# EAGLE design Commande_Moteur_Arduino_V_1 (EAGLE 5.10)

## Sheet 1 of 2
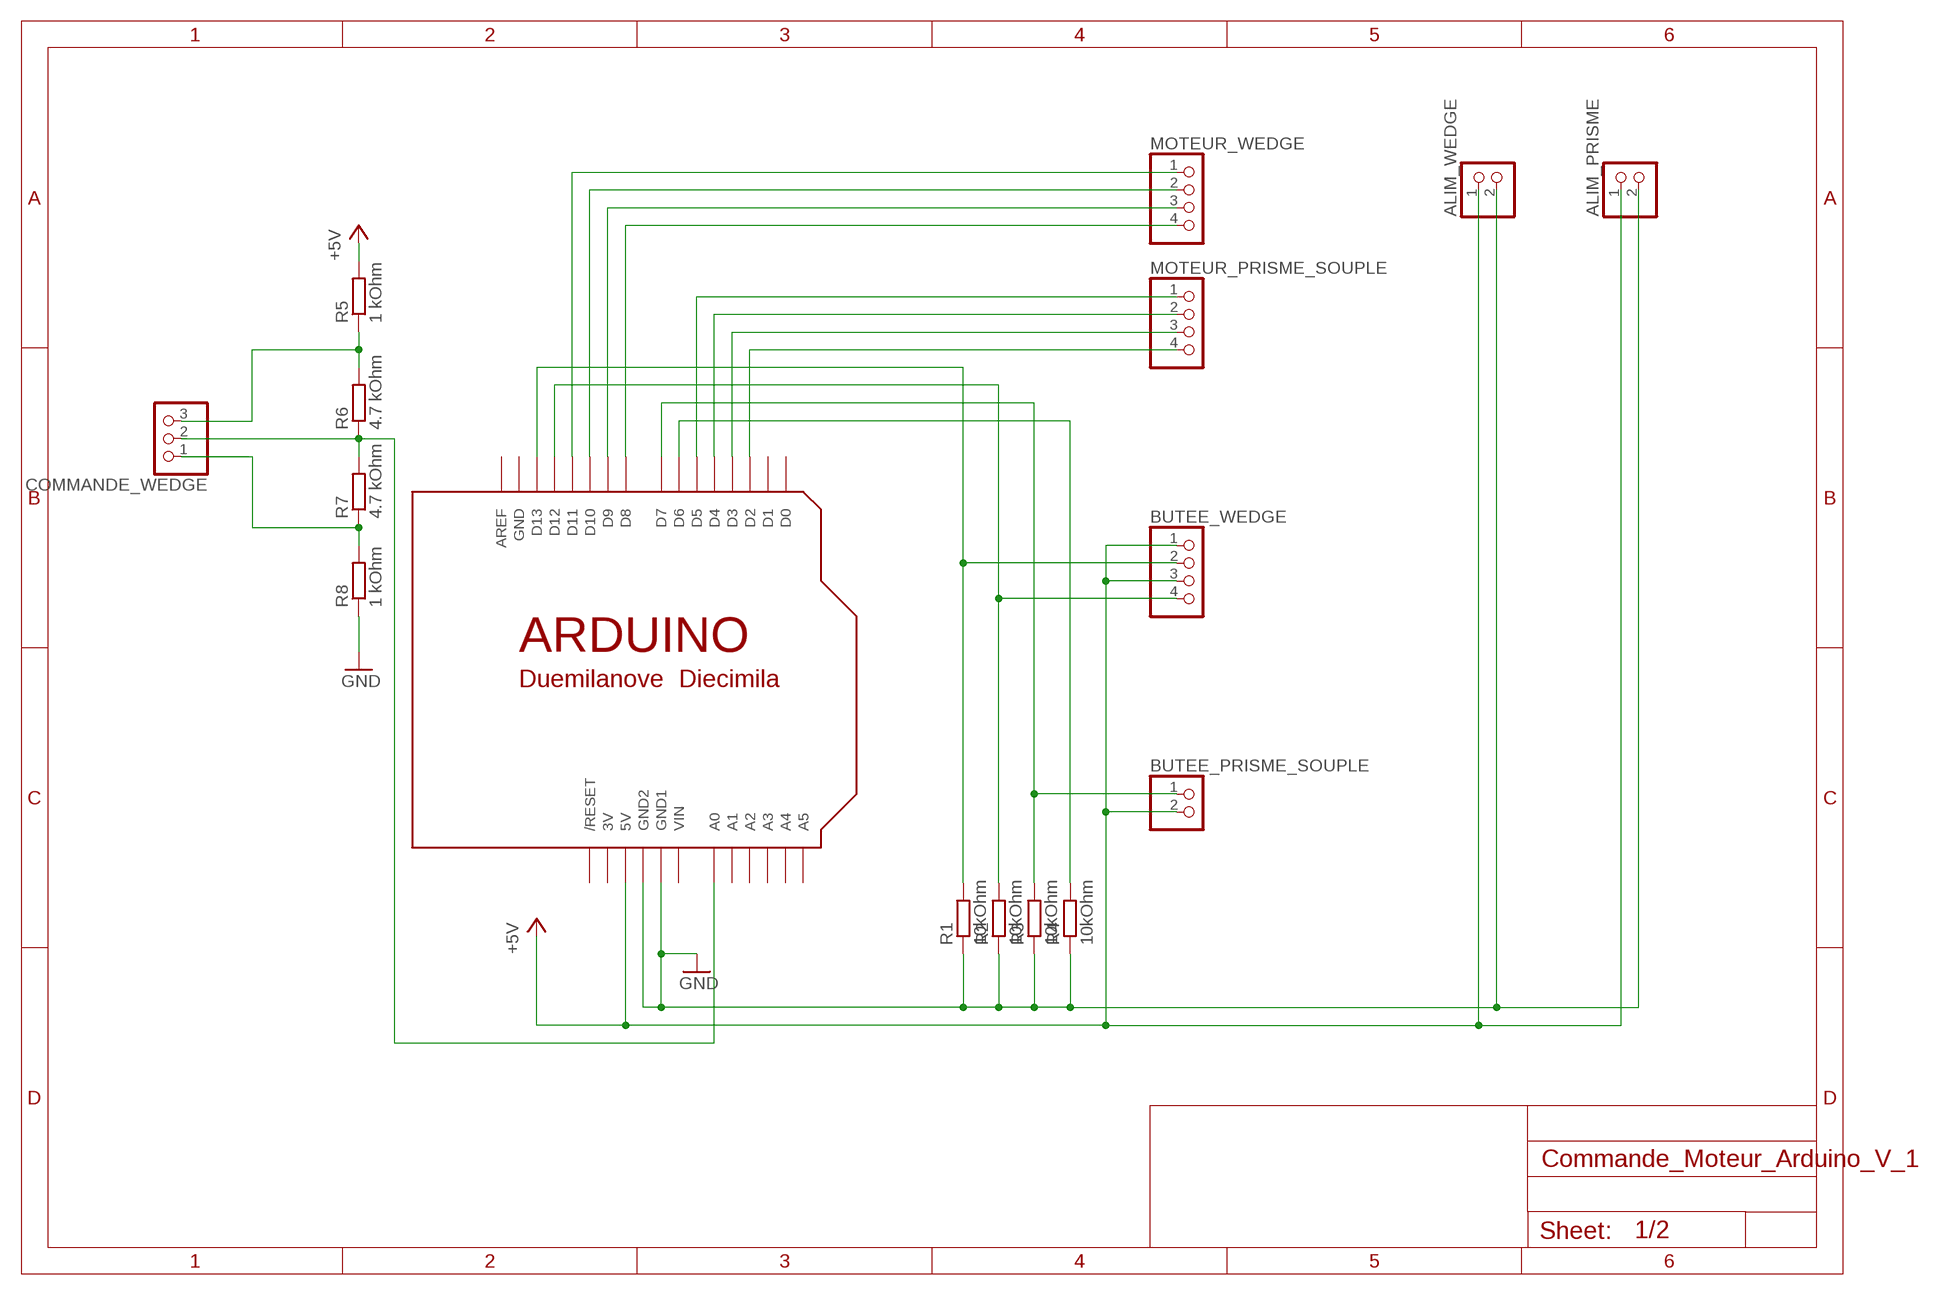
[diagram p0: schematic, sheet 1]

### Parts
ALIM_PRISME  PINHD-1X2  [1X02]
ALIM_WEDGE  PINHD-1X2  [1X02]
BUTEE_PRISME_SOUPLE  PINHD-1X2  [1X02]
BUTEE_WEDGE  PINHD-1X4  [1X04]
COMMANDE_WEDGE  PINHD-1X3  [1X03]
MOTEUR_PRISME_SOUPLE  PINHD-1X4  [1X04]
MOTEUR_WEDGE  PINHD-1X4  [1X04]
R1  10kOhm  R-EU_0204/7  [0204/7]
R2  10kOhm  R-EU_0204/7  [0204/7]
R3  10kOhm  R-EU_0204/7  [0204/7]
R4  10kOhm  R-EU_0204/7  [0204/7]
R5  1 kOhm  R-EU_0204/7  [0204/7]
R6  4.7 kOhm  R-EU_0204/7  [0204/7]
R7  4.7 kOhm  R-EU_0204/7  [0204/7]
R8  1 kOhm  R-EU_0204/7  [0204/7]
U$1  ARDUINOUNO  [ARDUINO]

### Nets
+5V: ALIM_PRISME.1 ALIM_WEDGE.1 BUTEE_PRISME_SOUPLE.2 BUTEE_WEDGE.1 BUTEE_WEDGE.3 R5.2 U$1.5V
GND: ALIM_PRISME.2 ALIM_WEDGE.2 R1.1 R2.1 R3.1 R4.1 R8.1 U$1.GND1 U$1.GND2
N$1: MOTEUR_WEDGE.4 U$1.D8
N$2: MOTEUR_WEDGE.3 U$1.D9
N$3: MOTEUR_WEDGE.2 U$1.D10
N$4: MOTEUR_WEDGE.1 U$1.D11
N$5: MOTEUR_PRISME_SOUPLE.4 U$1.D2
N$6: MOTEUR_PRISME_SOUPLE.3 U$1.D3
N$7: MOTEUR_PRISME_SOUPLE.2 U$1.D4
N$8: MOTEUR_PRISME_SOUPLE.1 U$1.D5
N$9: COMMANDE_WEDGE.3 R5.1 R6.2
N$10: BUTEE_WEDGE.2 R1.2 U$1.D13
N$11: BUTEE_WEDGE.4 R2.2 U$1.D12
N$12: BUTEE_PRISME_SOUPLE.1 R3.2 U$1.D7
N$13: R4.2 U$1.D6
N$14: COMMANDE_WEDGE.2 R6.1 R7.2 U$1.A0
N$15: COMMANDE_WEDGE.1 R7.1 R8.2
Unconnected: U$1.A1 U$1.A2 U$1.A3 U$1.A4 U$1.A5 U$1.AREF U$1.D0 U$1.D1 U$1.RESET(/RESET)

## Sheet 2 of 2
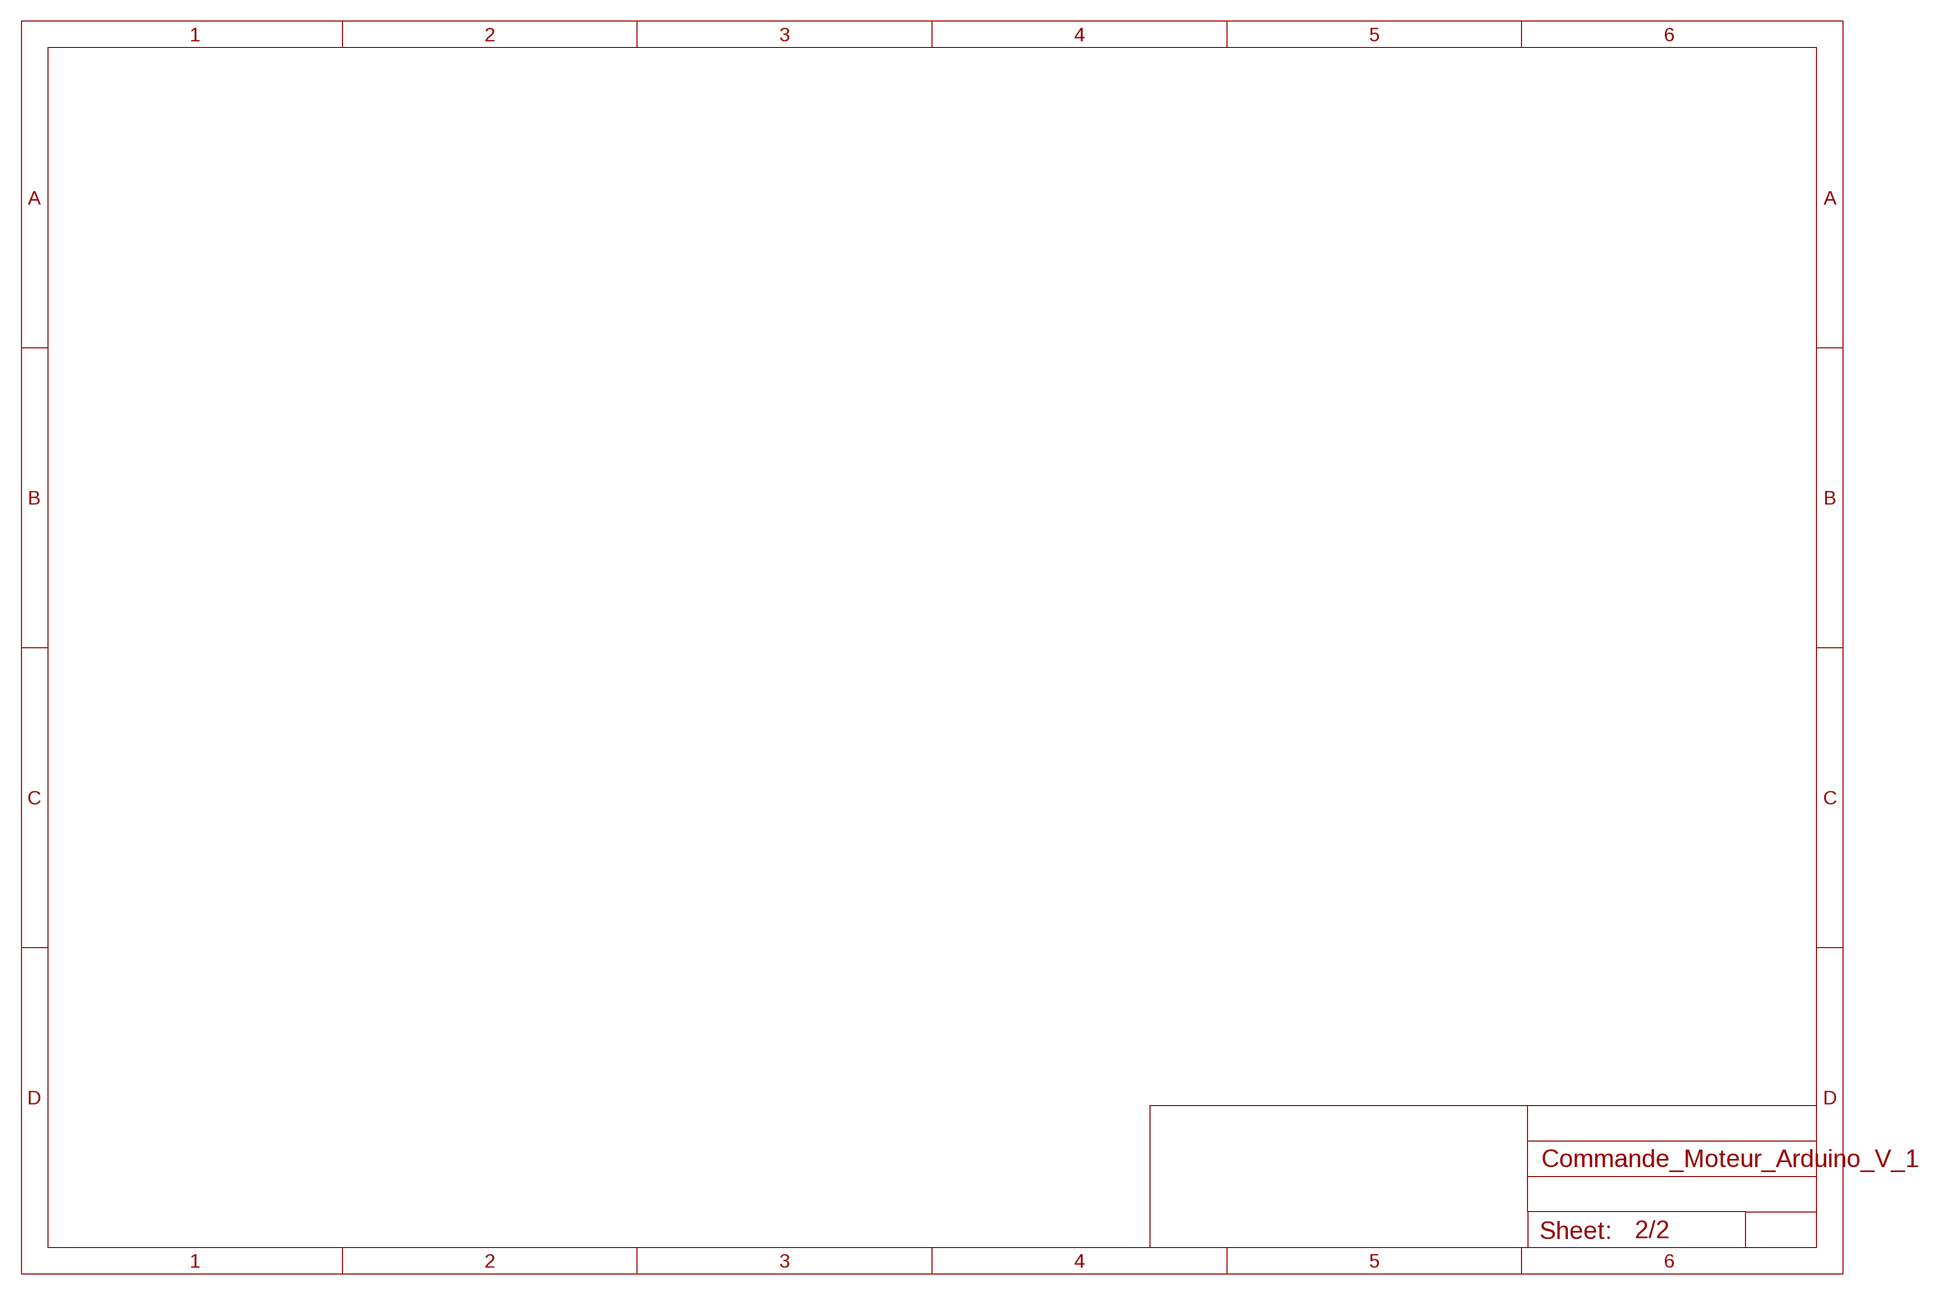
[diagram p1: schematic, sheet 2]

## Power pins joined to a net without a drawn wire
3V: U$1.3V
GND: U$1.GND
VIN: U$1.VIN

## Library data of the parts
ALIM_PRISME ALIM_WEDGE BUTEE_PRISME_SOUPLE = pinhead_btr:PINHD-1X2: PIN HEADER
BUTEE_WEDGE MOTEUR_PRISME_SOUPLE MOTEUR_WEDGE = pinhead_btr:PINHD-1X4: PIN HEADER
COMMANDE_WEDGE = pinhead_btr:PINHD-1X3: PIN HEADER
R1-R8 = rcl:R-EU_: RESISTOR, European symbol
U$1 = adafruit2:ARDUINO: Arduino Diecimila/Duemilanove Make a shield with ease, this package has all the named pins as well as the two mounting drill holes and an outline of the USB and DC power connector. The outline is on the DIMENSION layer, so if your board house uses it they will cut the outline to match.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

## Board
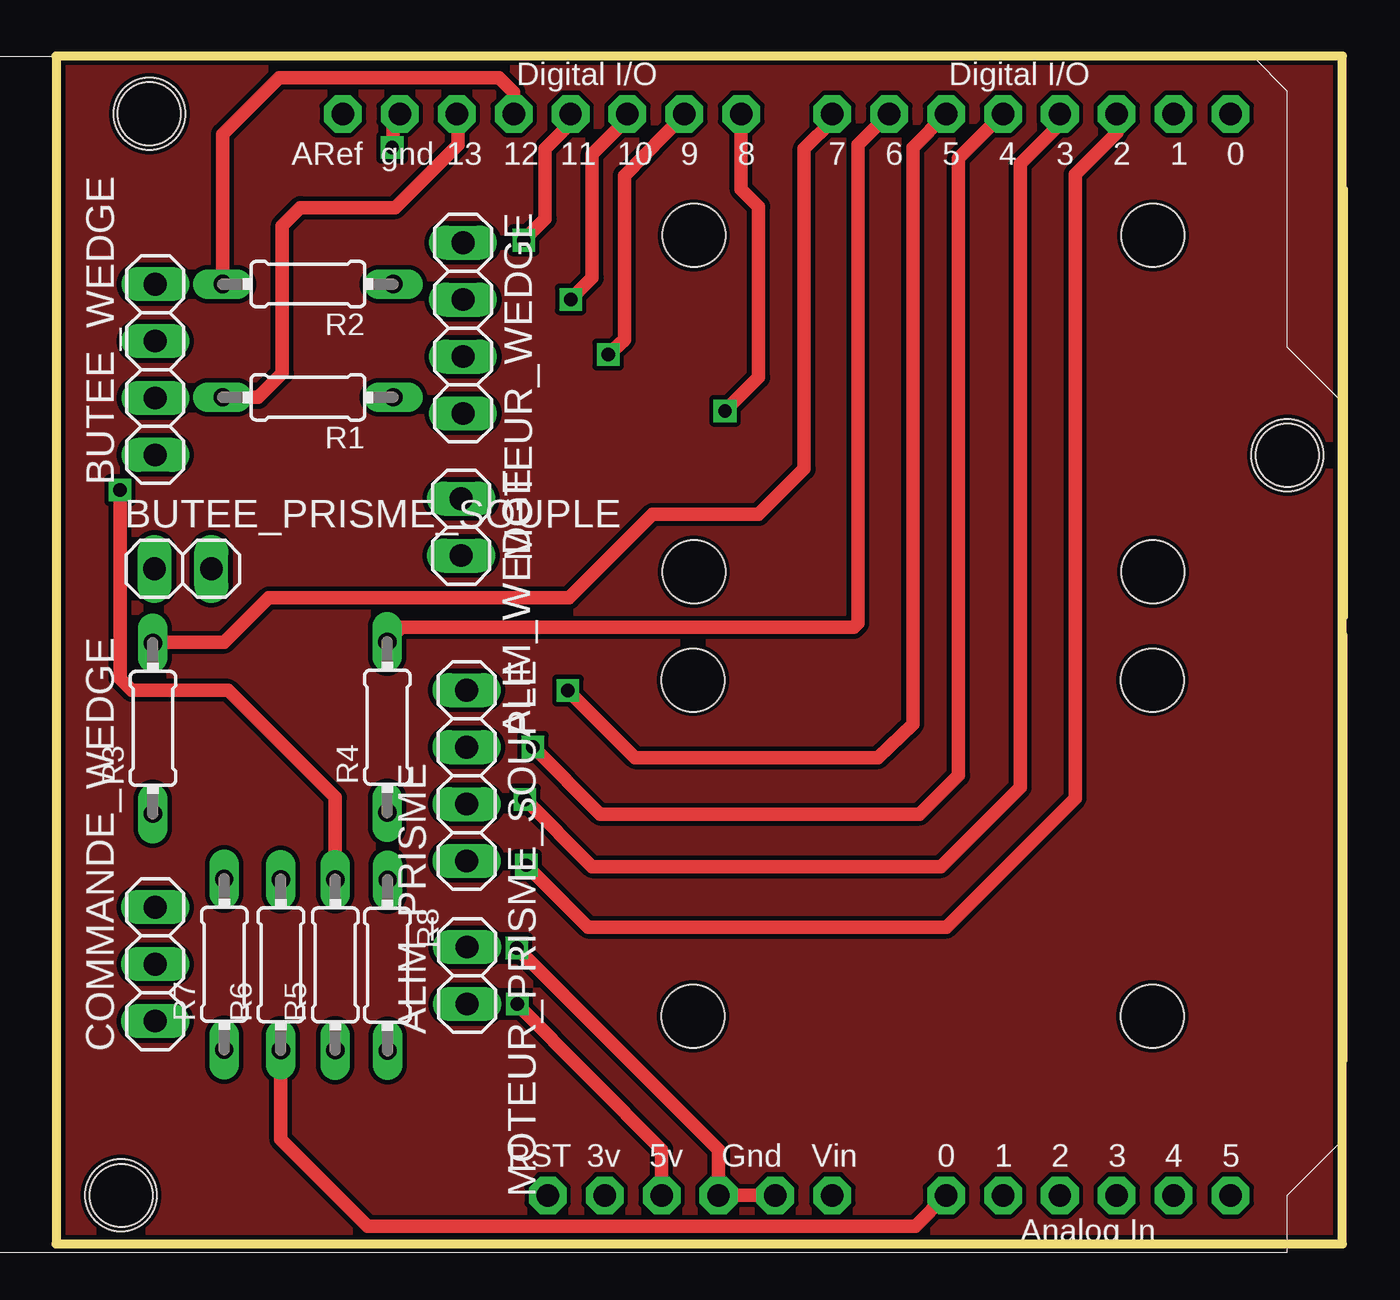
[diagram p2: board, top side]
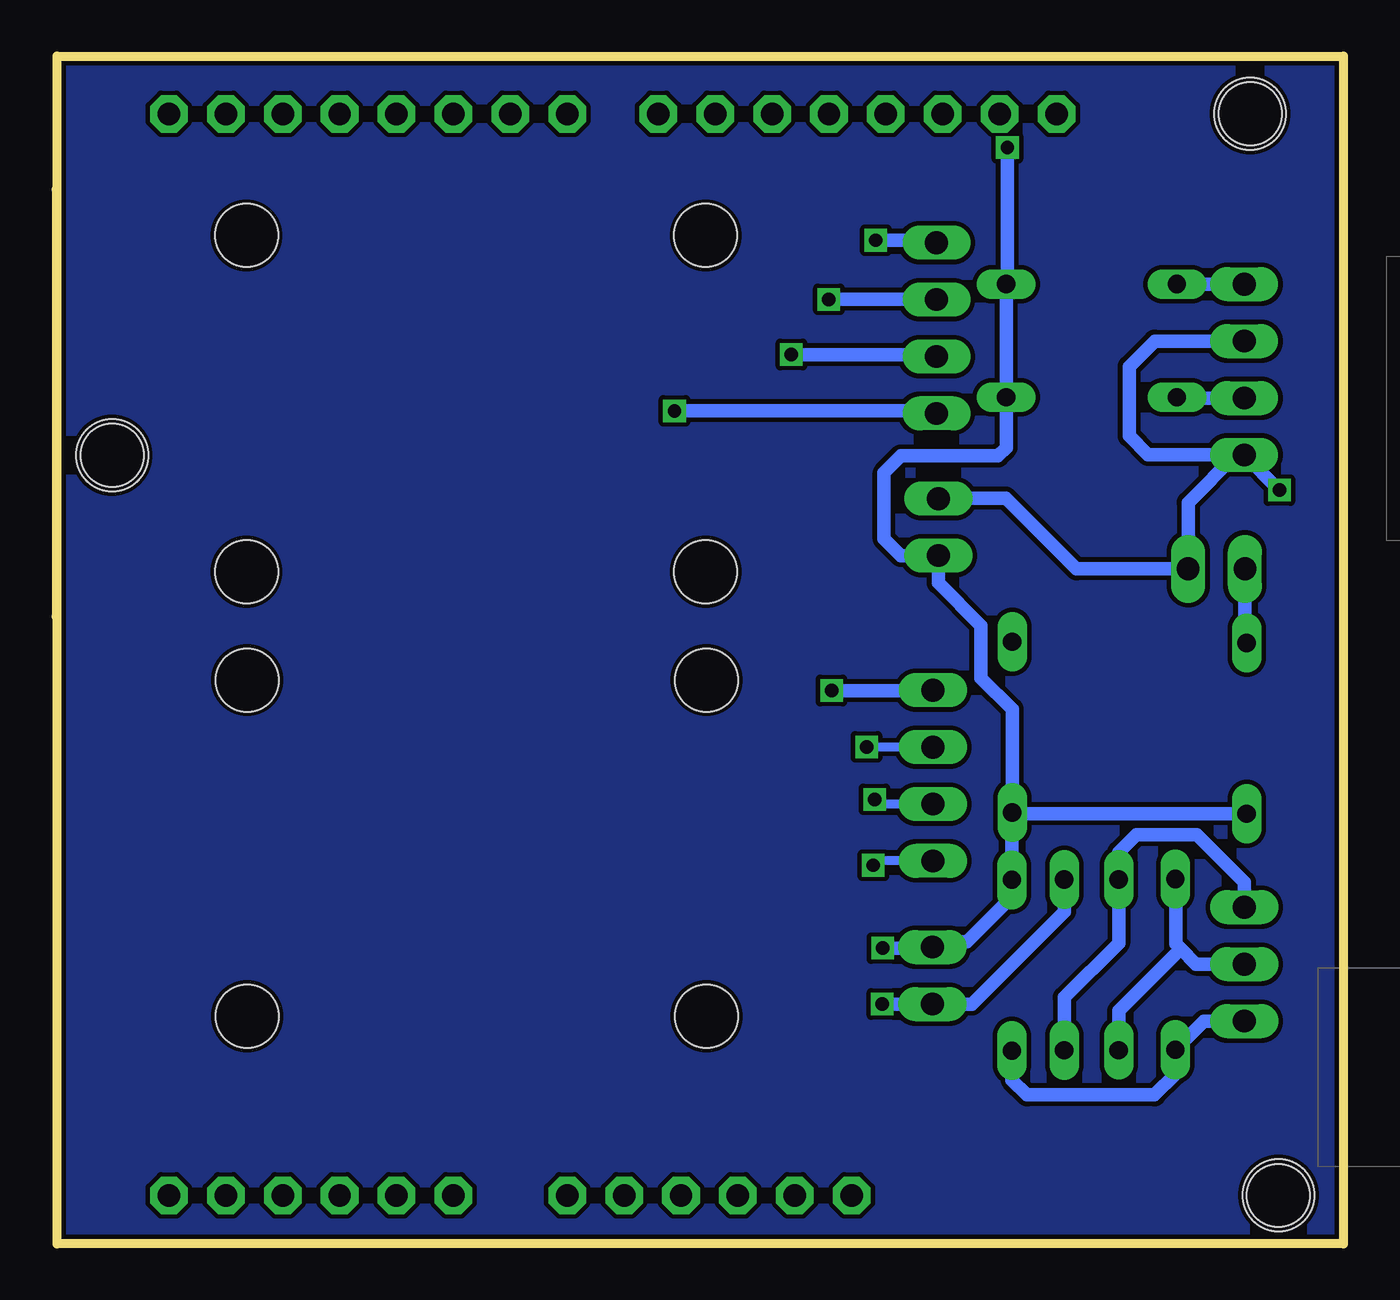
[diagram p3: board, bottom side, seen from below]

Size 57.47 x 53 mm. Coordinates in mm from the lower left corner, seen from the top.
Outline: 57.43,27.21 57.43,8.16
Outline: 57.47,47.05 57.47,28
Outline: 0,0 57.42,0 57.42,53 0,53 0,0
Copper layers (1*16): Top 0.035mm / dielectric 1.5mm / Bottom 0.035mm
Design rules "default *": minimum track width 10mil, minimum drill 24mil, track to track 8mil, track to pad 8mil, pad to pad 8mil, via to via 8mil, smd to smd 8mil, copper to edge 8mil, drill to drill 8mil, minimum pad ring 10mil, minimum via ring 8mil, stop-mask expansion 4mil, vias tented up to drill 0mil, thermal gap 10mil
Holes 2.8 mm at 48.93,10.16 48.93,25.16 28.43,10.16 28.43,25.16 48.97,29.99 48.97,44.99 28.47,29.99 28.47,44.99 4.17,50.42 2.9,2.16 54.96,35.19

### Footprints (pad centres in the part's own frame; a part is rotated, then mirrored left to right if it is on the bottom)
1X02 = drill 1.016 long: 1 -1.27,0; 2 1.27,0
1X04 = drill 1.016 long: 1 -3.81,0; 2 -1.27,0; 3 1.27,0; 4 3.81,0
1X03 = drill 1.016 long: 1 -2.54,0; 2 0,0; 3 2.54,0
0204/7 = drill 0.813 long: 1 -3.81,0; 2 3.81,0
ARDUINO = drill 1 pad 1.676 octagon: 3V 35.56,2.54; 5V 38.1,2.54; A0 50.8,2.54; A1 53.34,2.54; A2 55.88,2.54; A3 58.42,2.54; A4 60.96,2.54; A5 63.5,2.54; AREF 23.876,50.8; D0 63.5,50.8; D1 60.96,50.8; D2 58.42,50.8; D3 55.88,50.8; D4 53.34,50.8; D5 50.8,50.8; D6 48.26,50.8; D7 45.72,50.8; D8 41.656,50.8; D9 39.116,50.8; D10 36.576,50.8; D11 34.036,50.8; D12 31.496,50.8; D13 28.956,50.8; GND 26.416,50.8; GND1 43.18,2.54; GND2 40.64,2.54; RESET 33.02,2.54; VIN 45.72,2.54 | hole 3.2: 15.24,50.8; 66.04,35.56; 13.97,2.54

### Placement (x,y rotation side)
ALIM_PRISME  18.35,11.97 90 top
ALIM_WEDGE  18.08,31.98 270 top
BUTEE_PRISME_SOUPLE  5.67,30.12 0 top
BUTEE_WEDGE  4.43,39.01 90 top
COMMANDE_WEDGE  4.43,12.48 90 top
MOTEUR_PRISME_SOUPLE  18.33,20.89 270 top
MOTEUR_WEDGE  18.17,40.86 270 top
R1  11.24,37.77 180 top
R2  11.24,42.82 180 top
R3  4.33,23 90 top
R4  14.79,23.05 90 top
R5  12.47,12.45 90 top
R6  10.04,12.45 90 top
R7  7.51,12.47 90 top
R8  14.8,12.43 270 top
U$1  -11.07,-0.38 0 top

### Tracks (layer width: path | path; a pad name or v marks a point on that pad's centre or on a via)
+5V  (via drill 0.6)
  Top 0.61: v2.86,33.63 2.86,25.22 3.38,24.7 7.68,24.7 12.47,19.91 R5.2 | U$1.5V 27.03,4.21 v20.59,10.7 | ALIM_PRISME.1
  Bottom 0.61: BUTEE_WEDGE.3 8.43,40.28 9.56,39.14 9.56,36.05 8.72,35.21 4.45,35.21 BUTEE_WEDGE.1 | BUTEE_WEDGE.1 4.81,35.2 6.93,33.08 BUTEE_PRISME_SOUPLE.2 11.92,30.12 15.08,33.28 18.05,33.28 ALIM_WEDGE.1 | v2.86,33.63 BUTEE_WEDGE.1 | R5.2 12.46,14.83 16.59,10.7 ALIM_PRISME.1 v20.59,10.7
GND  (via drill 0.6)
  Top 0.61: U$1.GND 15.05,50.13 15.05,48.97 v15,48.92 | U$1.GND1 U$1.GND2 29.57,4.2 v20.57,13.2 | ALIM_PRISME.2 18.4,13.2
  Bottom 0.61: R3.1 14.73,19.19 R4.1 | R4.1 R8.1 14.8,15.49 16.82,13.47 18.12,13.47 ALIM_PRISME.2 18.4,13.2 v20.57,13.2 | R4.1 14.79,23.86 16.18,25.25 16.18,27.59 18.08,29.49 ALIM_WEDGE.2 | ALIM_WEDGE.2 | ALIM_WEDGE.2 19.76,30.71 20.51,31.46 20.51,34.41 19.76,35.16 15.43,35.16 15.06,35.53 R1.1 R2.1 15,42.88 v15,48.92
N$1  (via drill 0.6)
  Top 0.61: U$1.D8 30.59,47.05 31.36,46.28 31.36,38.66 v29.86,37.16 | MOTEUR_WEDGE.4 18.28,37.16
  Bottom 0.61: v29.86,37.16 18.28,37.16 MOTEUR_WEDGE.4
N$2  (via drill 0.6)
  Top 0.61: U$1.D9 28.05,50.4 25.37,47.66 25.37,40.34 v24.65,39.68 | MOTEUR_WEDGE.3 18.26,39.68
  Bottom 0.61: v24.65,39.68 18.26,39.68 MOTEUR_WEDGE.3
N$3  (via drill 0.6)
  Top 0.61: U$1.D10 25.51,50.19 23.93,48.62 23.93,43.1 v22.97,42.14 | MOTEUR_WEDGE.2
  Bottom 0.61: v22.97,42.14 MOTEUR_WEDGE.2
N$4  (via drill 0.6)
  Top 0.61: U$1.D11 22.97,49.99 21.83,48.86 21.83,45.74 v20.87,44.78 | MOTEUR_WEDGE.1 18.27,44.78
  Bottom 0.61: v20.87,44.78 18.27,44.78 MOTEUR_WEDGE.1
N$5  (via drill 0.6)
  Top 0.61: U$1.D2 47.35,49.57 45.5,47.72 45.5,19.89 39.75,14.13 23.75,14.13 v20.99,16.89
  Bottom 0.406: MOTEUR_PRISME_SOUPLE.4 20.99,17.08 v20.99,16.89
N$6  (via drill 0.6)
  Top 0.61: U$1.D3 44.81,49.97 43.04,48.2 43.04,20.37 39.51,16.83 23.93,16.83 v20.93,19.83
  Bottom 0.406: MOTEUR_PRISME_SOUPLE.3 20.93,19.62 v20.93,19.83
N$7  (via drill 0.6)
  Top 0.61: U$1.D4 40.29,48.44 40.29,20.91 38.55,19.17 24.29,19.17 v21.29,22.17 | MOTEUR_PRISME_SOUPLE.2
  Bottom 0.406: MOTEUR_PRISME_SOUPLE.2 v21.29,22.16 v21.29,22.17
N$8  (via drill 0.6)
  Top 0.61: U$1.D5 39.73,50.4 38.25,48.92 38.25,23.19 36.69,21.69 25.85,21.69 v22.85,24.69
  Bottom 0.406: MOTEUR_PRISME_SOUPLE.1
  Bottom 0.61: MOTEUR_PRISME_SOUPLE.1 v22.85,24.69
N$9
  Bottom 0.61: COMMANDE_WEDGE.3 4.43,16.13 6.55,18.26 9.26,18.26 10.04,17.47 R6.2 | R6.2 | R6.2 10.04,13.42 12.47,10.99 R5.1 | R5.1
N$10
  Top 0.61: R1.2 9.03,37.77 10.1,38.84 10.1,45.44 10.9,46.24 15.14,46.24 17.94,49.03 17.94,50.37 U$1.D13
  Bottom 0.61: BUTEE_WEDGE.2 7.44,37.74 R1.2
N$11
  Top 0.61: R2.2 7.43,49.52 9.95,52.03 19.79,52.03 20.44,51.38 U$1.D12
  Bottom 0.61: BUTEE_WEDGE.4 R2.2
N$12
  Top 0.61: U$1.D7 34.65,50.11 33.4,48.86 33.4,34.58 31.36,32.55 26.63,32.55 22.91,28.83 9.49,28.83 7.51,26.85 4.36,26.85 R3.2
  Bottom 0.61: BUTEE_PRISME_SOUPLE.1 4.4,26.88 R3.2
N$13
  Top 0.61: U$1.D6 37.18,50.42 35.79,49.04 35.79,27.69 35.61,27.51 15.43,27.51 R4.2
N$14
  Top 0.61: R6.1 10.04,4.66 13.92,0.78 38.35,0.78 U$1.A0
  Bottom 0.61: COMMANDE_WEDGE.2 6.59,12.48 7.27,13.16 | 7.27,13.16 7.49,13.38 7.49,16.26 R7.2 | R6.1 10.04,10.39 7.27,13.16
N$15
  Bottom 0.61: COMMANDE_WEDGE.1 6.23,9.94 R7.1 7.51,7.56 8.43,6.64 14.13,6.64 14.79,7.3 R8.2
N$16
  pour Bottom: 0.01,52.96 57.46,52.96 57.46,0.04 0.01,0.04
N$17
  pour Top: -0.05,53.04 57.39,53.04 57.46,0.09 0.02,0.09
